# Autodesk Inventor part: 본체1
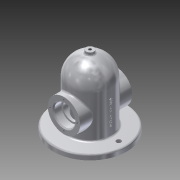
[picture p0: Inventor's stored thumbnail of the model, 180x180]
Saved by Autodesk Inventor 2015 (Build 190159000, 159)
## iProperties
Created: 2019-11
Part Number: 본체1
Material: 알루미늄 6061
Document SubType Name: Modeling
Designer: now
Density: 2.7 g/cm^3
Appearance: 알루미늄 - 평지
Mass: 1105.07 g
Surface Area: 881.878 cm^2
Volume: 409.284 cm^3
Author: now
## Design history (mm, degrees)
sketch "스케치1"
  geometry: C1 r 70 at (0, 0); 1 further point
  constraints: 1 centre point, 1 coincident
  dimensions: "d0" = 140 diameter of C1
extrude "돌출1" new body sketch "스케치1" distance "d1" = 10; taper "d2" = 0 deg
sketch "스케치2"
  geometry: C1 r 70 at (0, 0) reference; C2 r 40 at (0, 0)
  constraints: 1 centre point, 1 coincident
  dimensions: "d3" = 80 diameter of C2
extrude "돌출2" join sketch "스케치2" distance "d4" = 120; taper "d5" = 0 deg
fillet "모깎기1" dims "d6" = 40
node "작업 평면1"
sketch "스케치3"
  geometry: C1 r 7.5 at (0, 0); 1 further point
  constraints: 1 centre point, 1 coincident
  dimensions: "d8" = 15 diameter of C1
extrude "돌출3" join sketch "스케치3" stored distance "d9" = 130; taper "d10" = 0 deg
feature "쉘1" dims "d11" = 10
sketch "스케치5"
  geometry: C1 r 7.5 at (0, 0) reference
hole "구멍1" sketch "스케치5" at (0, 0) diameter "d12" = 5.188; stored, may be unused: countersink angle "d16" = 90 deg, drill point angle "d18" = 118 deg; dims "d13" = 12, "d14" = 4, "d15" = 2, "d17" = 16
node "작업 평면2"
sketch "스케치6"
  geometry: L1 (-70, 0)-(70, 0) reference; C1 r 31 at (0, 50); 2 further points
  constraints: 1 centre point, 1 midpoint, 1 vertical alignment
  dimensions: "d20" = 62 diameter of C1; "d21" = 50 distance from line of L1 C1.centre
extrude "돌출4" join sketch "스케치6" stored distance "d22" = 130; taper "d23" = 0 deg
sketch "스케치7"
  geometry: C1 r 31 at (0, 0) reference; C2 r 20 at (0, 0); 1 further point
  constraints: 1 centre point, 1 coincident
  dimensions: "d24" = 40 diameter of C2
extrude "돌출5" cut sketch "스케치7" distance "d25" = 15; taper "d26" = 0 deg
sketch "스케치8"
  geometry: C1 r 20 at (0, 0) reference; C2 r 16.5 at (0, 0); 1 further point
  constraints: 1 centre point, 1 coincident
  dimensions: "d27" = 33 diameter of C2
extrude "돌출6" cut sketch "스케치8" stored distance "d28" = 15; taper "d29" = 0 deg
sketch "스케치9"
  geometry: C1 r 40 at (0, 0) reference; 2 further points
  constraints: 2 horizontal alignment
  dimensions: "d30" = 55 distance of C1.centre point (-55, 0); "d31" = 55 distance of C1.centre point (55, 0)
hole "구멍2" sketch "스케치9" at (-55, 0), (55, 0) diameter "d32" = 9; stored, may be unused: countersink angle "d36" = 90 deg, drill point angle "d38" = 118 deg; dims "d33" = 12, "d34" = 4, "d35" = 2, "d37" = 16
sketch "스케치10"
  geometry: C1 r 20 at (0, 0) reference; 2 further points
  constraints: 1 vertical alignment
  dimensions: "d39" = 26 distance of C1.centre point (0, 26)
hole "구멍3" sketch "스케치10" at (0, 26) diameter "d40" = 3.242; stored, may be unused: countersink angle "d44" = 90 deg, drill point angle "d46" = 118 deg; dims "d41" = 8, "d42" = 4, "d43" = 2, "d45" = 10
node "작업 평면3"
sketch "스케치11"
  geometry: L1 (-70, 0)-(70, 0) reference; 3 further points
  constraints: 1 midpoint, 1 vertical alignment, 1 other
  dimensions: "d51" = 50 distance from line of L1 point (0, 50)
feature "엠보싱1" sketch "스케치11" dims "d52" = 0.5, "d53" = 0
fillet "모깎기2" dims "d54" = 3
fillet "모깎기3" dims "d55" = 3
fillet "모깎기4" dims "d56" = 0.3
chamfer "모따기1" distance "d57" = 2; stored, may be unused: second distance "d58" = 2, angle "d59" = 45 deg
node "솔리드1"
mirror "대칭1"
pattern_circular "원형 패턴1" dims angle "d48" = 360 deg
mirror "대칭2"
other parameters: "d7" = 135
